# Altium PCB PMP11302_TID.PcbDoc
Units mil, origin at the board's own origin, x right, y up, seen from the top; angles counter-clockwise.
Board outline 1771.65 x 1496.06 mil, 2 copper layers (Top Layer, Bottom Layer), stack 62 mil thick; 48 components, 26 nets, 99 pads, 6 vias.
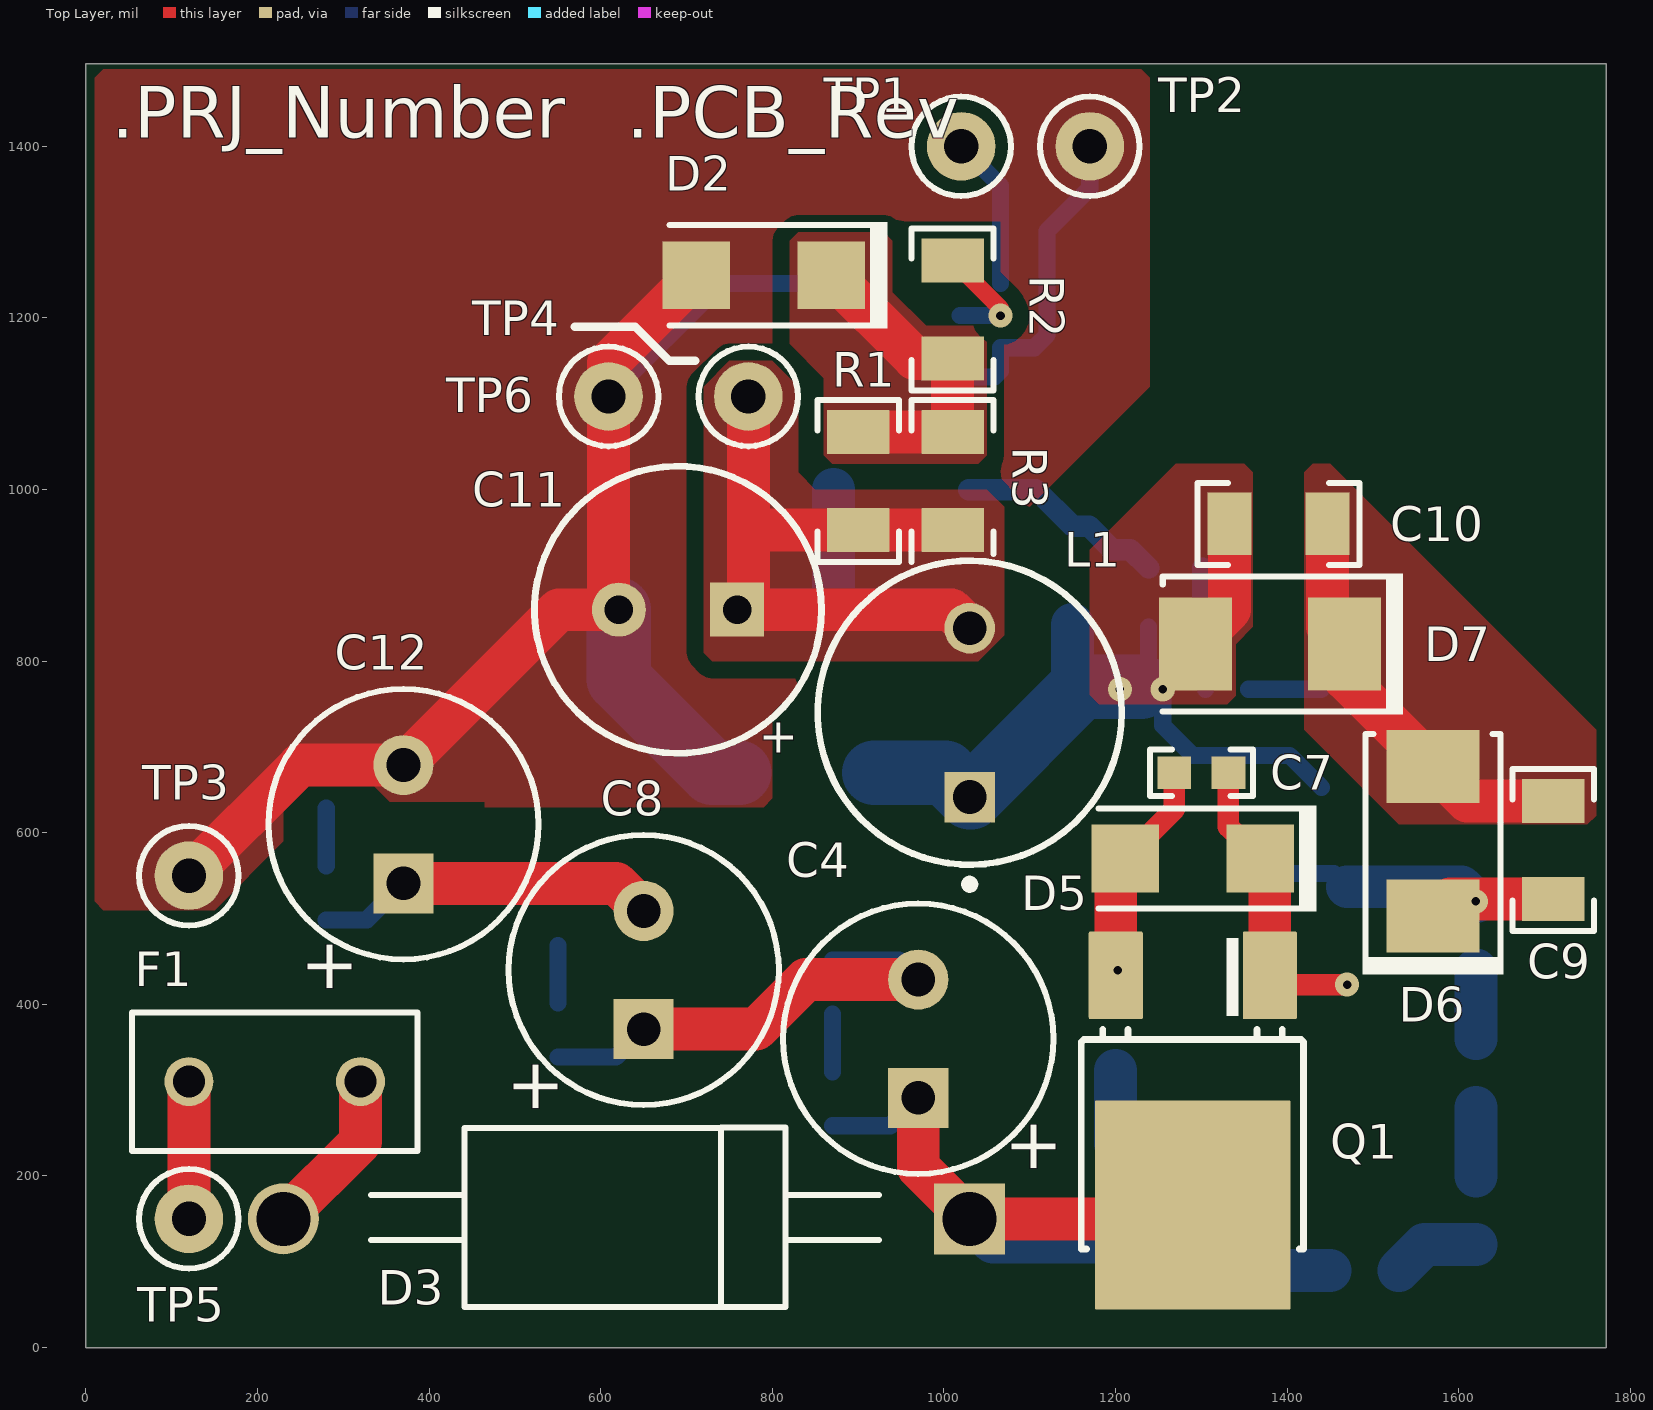
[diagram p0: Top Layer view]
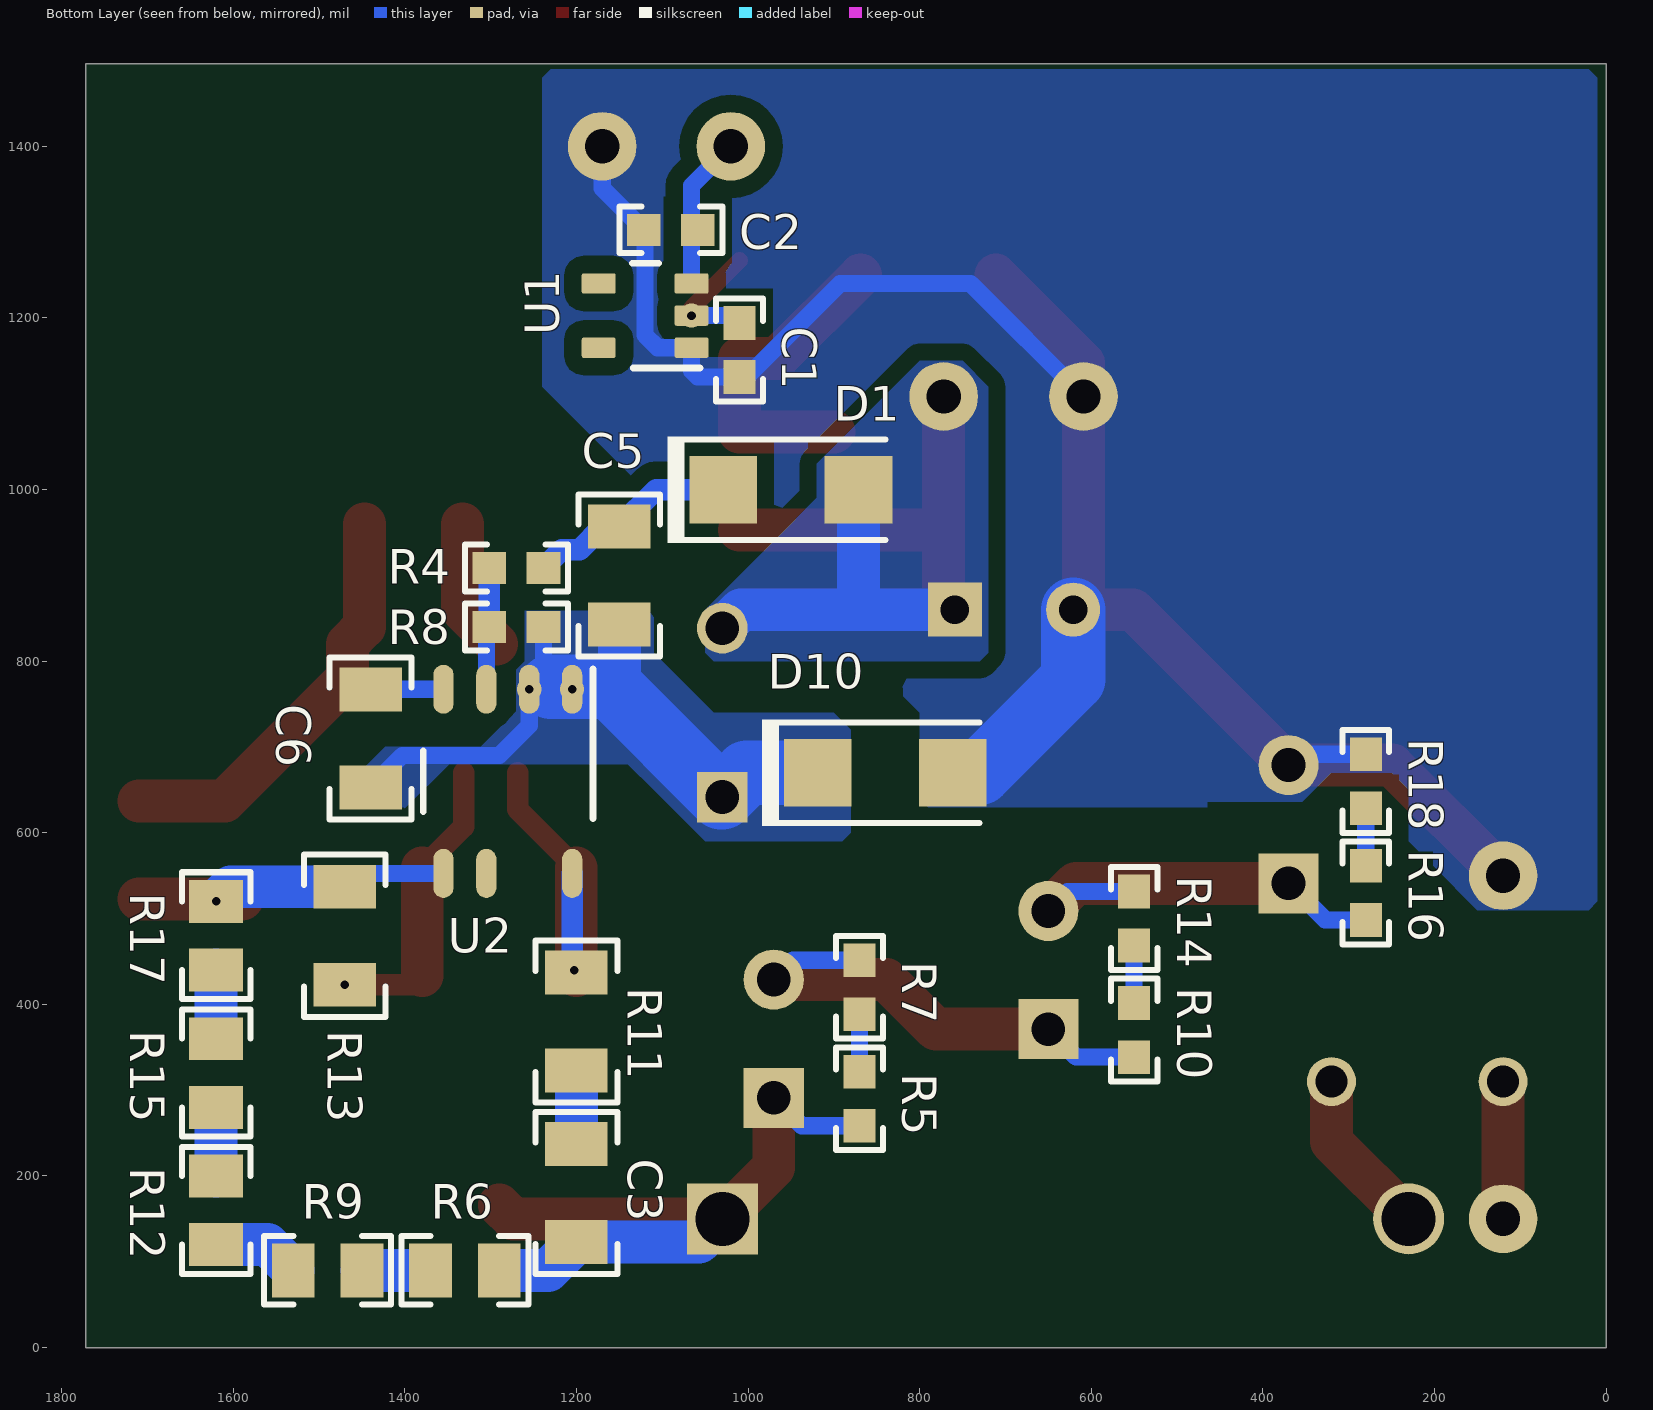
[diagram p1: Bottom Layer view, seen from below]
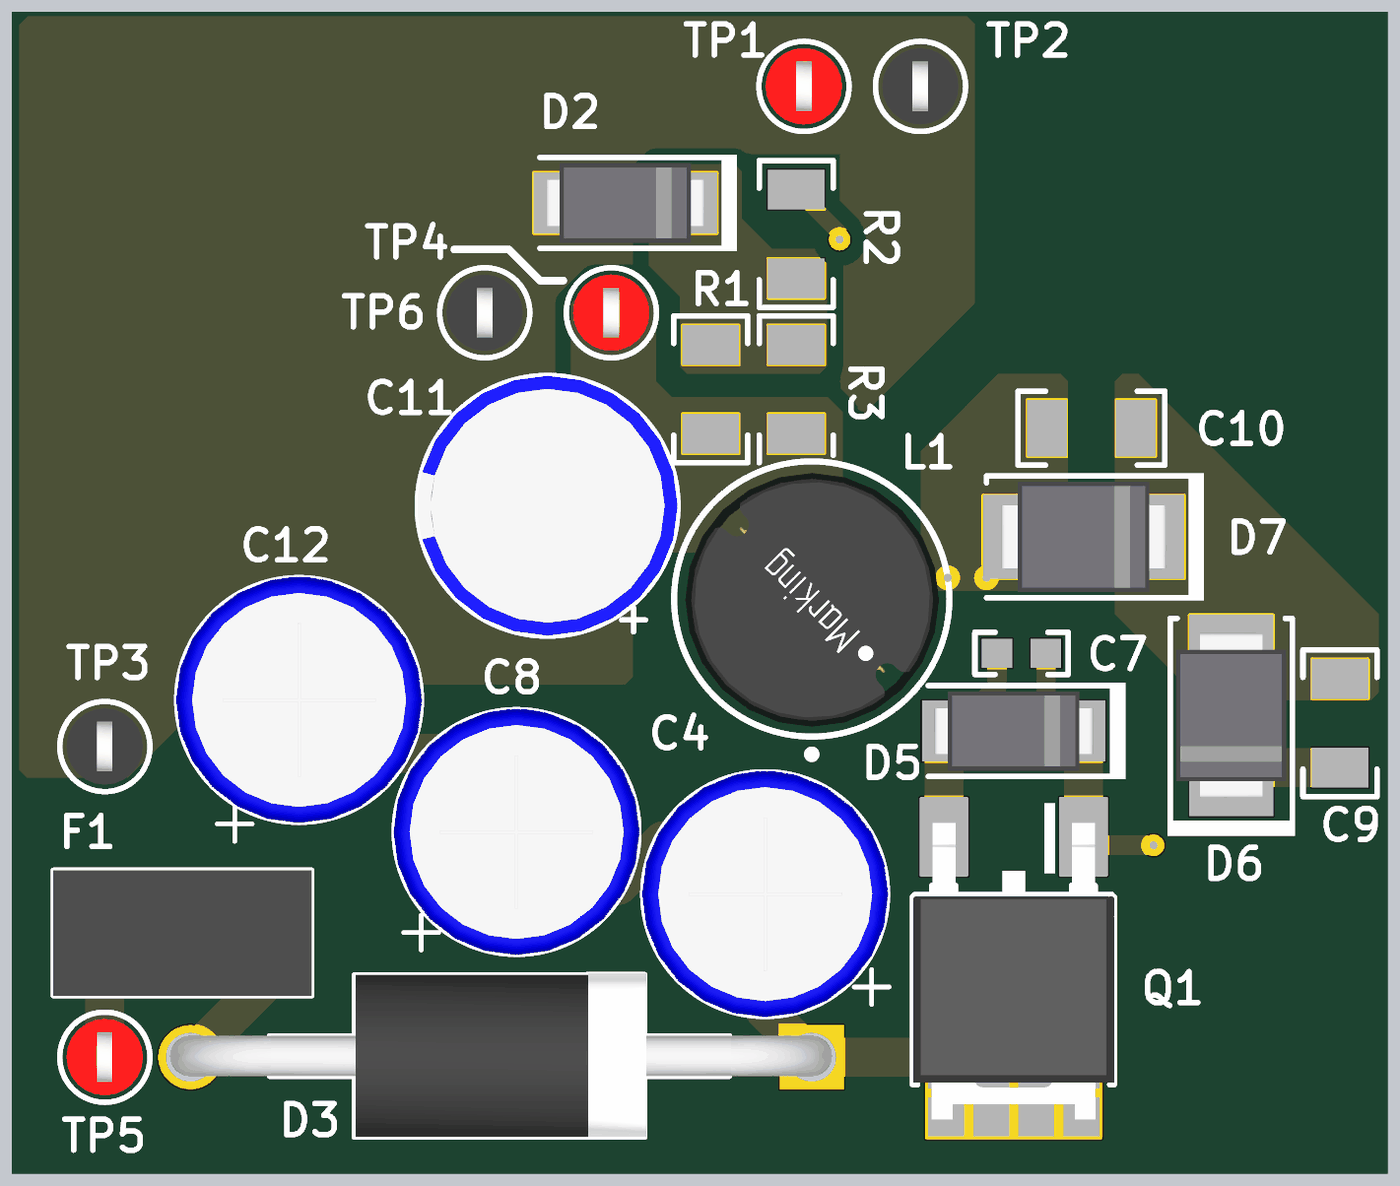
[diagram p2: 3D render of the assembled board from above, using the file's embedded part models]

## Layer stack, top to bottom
Top Solder: solder mask 0.4, Solder Resist, Dk 3.5
Top Layer: signal copper 1.4
Dielectric1: core 59.2, FR-4, Dk 4.8
Bottom Layer: signal copper 1.4
Bottom Solder: solder mask 0.4, Solder Resist, Dk 3.5

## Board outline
0,0 1771.65,0 1771.65,1496.06 0,1496.06

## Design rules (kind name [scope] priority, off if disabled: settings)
AcuteAngle [All] p1: minimum=4.50000000000000E+0001 checktracksonly=FALSE
AssemblyTestPointUsage [All] p1: valid=2
Clearance Clearance_1 [InNetClass('HV') vs InNet('GND')] p1: gap=60
Clearance Clearance_Keepouts [((IsTrack Or IsArc) And Not InPoly) And IsFree and IsKeepOut vs ((IsTrack Or IsArc) And Not InPoly) And IsFree and IsKeepOut] p2: gap=0
Clearance Clearance_BoardEdge_MountingHoles [OnCopper and InComponentClass('Mounting Holes') vs IsKeepOut] p3: gap=40
Clearance Clearance_BoardEdge_Poly [OnCopper and InPoly vs IsKeepOut] p4: gap=25
Clearance Clearance_BoardEdge [OnCopper and Not InComponentClass('Logo') and not InComponentClass('FiducialMark') and not InRegion(1000,500,4000,800) and Not IsKeepout vs IsKeepOut] p5: gap=75
Clearance Clearance_Poly [InPolygon] p6: gap=20
Clearance [All] p7: gap=7.87
ComponentClearance ComponentClearance_MountingHoles_FiducialMarks [InComponentClass('Mounting Holes') vs InComponentClass('FiducialMark')] p1: gap=20 collisioncheckmode=3 verticalgap=10 showdistances=FALSE
ComponentClearance ComponentClearance_Shunt [InComponentClass('Header') vs InComponentClass('Shunt')] p2: gap=0 collisioncheckmode=3 verticalgap=0 showdistances=FALSE
ComponentClearance ComponentClearance_Logo [InComponentClass('Logo')] p3: gap=5 collisioncheckmode=3 verticalgap=10 showdistances=FALSE
ComponentClearance ComponentClearance_ScrewToNut [(HasFootprint('NY PMS 440 0025 PH')) vs (HasFootprint('Keystone_1902C'))] p4: gap=20 collisioncheckmode=3 verticalgap=100000 showdistances=FALSE
ComponentClearance ComponentClearance_MountingHoles [InComponentClass('Mounting Holes')] p5: gap=20 collisioncheckmode=3 verticalgap=10 showdistances=FALSE
ComponentClearance ComponentClearance_SmallPassives [HasFootprint('0201*') or HasFootprint('0402*') or HasFootprint('0508') or HasFootprint('0603*') or HasFootprint('0612') or HasFootprint('0805*') or HasFootprint('0815*') or HasFootprint('0830*') or HasFootprint('1206*') or HasFootprint('1210*') or HasFootprint('1808*') or HasFootprint('1812*') or HasFootprint('1825*') or HasFootprint('2010*') or HasFootprint('2220*') or HasFootprint('2225*') or HasFootprint('2512*') or HasFootprint('2728*') or HasFootprint('3518*') vs HasFootprint('0201*') or HasFootprint('0402*') or HasFootprint('0508') or HasFootprint('0603*') or HasFootprint('0612') or HasFootprint('0805*') or HasFootprint('0815*') or HasFootprint('0830*') or HasFootprint('1206*') or HasFootprint('1210*') or HasFootprint('1808*') or HasFootprint('1812*') or HasFootprint('1825*') or HasFootprint('2010*') or HasFootprint('2220*') or HasFootprint('2225*') or HasFootprint('2512*') or HasFootprint('2728*') or HasFootprint('3518*')] p6: gap=20 collisioncheckmode=3 verticalgap=20 showdistances=FALSE
ComponentClearance ComponentClearance_THtoSMT [IsThruComponent vs IsSMTComponent] p7: gap=10 collisioncheckmode=3 verticalgap=10 showdistances=FALSE
ComponentClearance ComponentClearance_THtoTH [IsThruComponent vs IsThruComponent] p8: gap=10 collisioncheckmode=3 verticalgap=10 showdistances=FALSE
ComponentClearance [All] p9: gap=10 collisioncheckmode=3 verticalgap=10 showdistances=FALSE
DiffPairsRouting [All] p1: maxlimit=100 minlimit=10 mostfreqgap=10 toplayer_minwidth=15 toplayer_maxwidth=15 toplayer_prefwidth=15 bottomlayer_minwidth=15 bottomlayer_maxwidth=15 bottomlayer_prefwidth=15 maxuncoupledlength=1000
FabricationTestPointUsage TestPointUsage [All] p1: valid=2 allowmultiple=FALSE
FabricationTestpoint Testpoint [All] p1: side=3 testpointundercomponent=TRUE minsize=40 maxsize=100 preferedsize=60 minholesize=0 maxholesize=40 preferedholesize=32 testpointgrid=1 allowsidetop=TRUE allowsidebottom=TRUE usegrid=TRUE gridtolerance=0.01
FanoutControl Fanout_LCC [IsLCC] p1: bgadir=Out bgaviamode=Centered fanoutstyle=Auto fanoutdirection=Alternating viagrid=1 // Fanout_LCC (Default Rule)
FanoutControl Fanout_BGA [IsBGA] p2: bgadir=Out bgaviamode=Centered fanoutstyle=Auto fanoutdirection=Alternating viagrid=1 // Fanout_BGA (Default Rule)
FanoutControl Fanout_Default [All] p4: bgadir=Out bgaviamode=Centered fanoutstyle=Auto fanoutdirection=Alternating viagrid=1 // Fanout_Default (Default Rule)
FanoutControl Fanout_Small [(CompPinCount < 5)] p5: bgadir=Out bgaviamode=Centered fanoutstyle=Auto fanoutdirection=OutThenIn viagrid=1 // Fanout_Small (Default Rule)
Height [All] p1: minheight=0 maxheight=3000 prefheight=500
HoleSize [All] p1: absolutevalues=TRUE maxlimit=251 minlimit=7 maxpercent=80.000 minpercent=20.000
MinimumAnnularRing MinimumAnnularRing_ThermalPadVias [IsVia and InAnyComponent] p1: minimumring=5.91
MinimumAnnularRing [All] p2: minimumring=9
MinimumSolderMaskSliver MinimumSolderMaskSliver_Logo [InComponentClass('Logo') vs InComponentClass('Logo')] p1: minsoldermaskwidth=0.7
MinimumSolderMaskSliver [All] p2: minsoldermaskwidth=2
PlaneConnect [All] p1: planeconnectstyle=Relief reliefexpansion=10 reliefentries=4 reliefconductorwidth=10 reliefairgap=10
PolygonConnect PolygonConnect_7 [All vs IsNamedPolygon('C9_2') Or  IsNamedPolygon('C5_2') Or  IsNamedPolygon('C11_1') Or  IsNamedPolygon('D2_1')] p1: connectstyle=Direct reliefconductorwidth=10 reliefentries=4 polygonreliefangle="90 Angle" airgapwidth=10
PolygonConnect PolygonConnect_6 [All vs IsNamedPolygon('GND2') Or  IsNamedPolygon('SGND') Or  IsNamedPolygon('GND1') Or  IsNamedPolygon('C901_1') Or  IsNamedPolygon('SGND') Or  IsNamedPolygon('GND2') Or  IsNamedPolygon('GND1')] p2: connectstyle=Direct reliefconductorwidth=10 reliefentries=4 polygonreliefangle="90 Angle" airgapwidth=10
PolygonConnect PolygonConnect_5 [All vs IsNamedPolygon('GND1') Or  IsNamedPolygon('GND1')] p3: connectstyle=Direct reliefconductorwidth=10 reliefentries=4 polygonreliefangle="90 Angle" airgapwidth=10
PolygonConnect PolygonConnect_4 [All vs IsNamedPolygon('C21_1') Or  IsNamedPolygon('C5_1') Or  IsNamedPolygon('C12_2') Or  IsNamedPolygon('C2_2') Or  IsNamedPolygon('C13_1') Or  IsNamedPolygon('C28_1') Or  IsNamedPolygon('C6_1') Or  IsNamedPolygon('GND') Or  IsNamedPolygon('GND2') Or  IsNamedPolygon('C14_1') Or  IsNamedPolygon('C13_1') Or  IsNamedPolygon('Q1_3') Or  IsNamedPolygon('C14_1') Or  IsNamedPolygon('C5_1') Or  IsNamedPolygon('GND2') Or  IsNamedPolygon('C28_1') Or  IsNamedPolygon('D5_2') Or  IsNamedPolygon('D6_2') Or  IsNamedPolygon('D2_1') Or  IsNamedPolygon('C12_2') Or  IsNamedPolygon('D2_1') Or  IsNamedPolygon('C4_1') Or  IsNamedPolygon('C4_1') Or  IsNamedPolygon('C2_2') Or  IsNamedPolygon('GND') Or  IsNamedPolygon('C33_1') Or  IsNamedPolygon('C9_1')] p4: connectstyle=Direct reliefconductorwidth=10 reliefentries=4 polygonreliefangle="90 Angle" airgapwidth=10
PolygonConnect PolygonConnect_3 [All vs IsNamedPolygon('C28_1') Or  IsNamedPolygon('C12_2') Or  IsNamedPolygon('C28_1') Or  IsNamedPolygon('C9_1') Or  IsNamedPolygon('D5_2') Or  IsNamedPolygon('C12_2') Or  IsNamedPolygon('C2_2') Or  IsNamedPolygon('C14_1') Or  IsNamedPolygon('C4_1') Or  IsNamedPolygon('C14_1') Or  IsNamedPolygon('D6_2') Or  IsNamedPolygon('GND2') Or  IsNamedPolygon('Q1_3') Or  IsNamedPolygon('C5_1') Or  IsNamedPolygon('D2_1') Or  IsNamedPolygon('C4_1') Or  IsNamedPolygon('C13_1') Or  IsNamedPolygon('C5_1') Or  IsNamedPolygon('C13_1') Or  IsNamedPolygon('C33_1') Or  IsNamedPolygon('D2_1') Or  IsNamedPolygon('GND') Or  IsNamedPolygon('GND') Or  IsNamedPolygon('GND2') Or  IsNamedPolygon('C2_2') Or  IsNamedPolygon('C6_1') Or  IsNamedPolygon('C21_1')] p5: connectstyle=Direct reliefconductorwidth=10 reliefentries=4 polygonreliefangle="90 Angle" airgapwidth=10
PolygonConnect PolygonConnect_2 [All vs IsNamedPolygon('C21_1') Or  IsNamedPolygon('C4_1') Or  IsNamedPolygon('D5_2') Or  IsNamedPolygon('C5_1') Or  IsNamedPolygon('C14_1') Or  IsNamedPolygon('C13_1') Or  IsNamedPolygon('C4_1') Or  IsNamedPolygon('C33_1') Or  IsNamedPolygon('C12_2') Or  IsNamedPolygon('D2_1') Or  IsNamedPolygon('C2_2') Or  IsNamedPolygon('C28_1') Or  IsNamedPolygon('C12_2') Or  IsNamedPolygon('D2_1') Or  IsNamedPolygon('C5_1') Or  IsNamedPolygon('Q1_3') Or  IsNamedPolygon('GND') Or  IsNamedPolygon('D6_2') Or  IsNamedPolygon('C6_1') Or  IsNamedPolygon('C2_2') Or  IsNamedPolygon('C14_1') Or  IsNamedPolygon('C28_1') Or  IsNamedPolygon('C13_1') Or  IsNamedPolygon('C9_1') Or  IsNamedPolygon('GND')] p6: connectstyle=Direct reliefconductorwidth=10 reliefentries=4 polygonreliefangle="90 Angle" airgapwidth=10
PolygonConnect PolygonConnect_1 [All vs IsNamedPolygon('C28_1') Or  IsNamedPolygon('D5_2') Or  IsNamedPolygon('C5_1') Or  IsNamedPolygon('C5_1') Or  IsNamedPolygon('D2_1') Or  IsNamedPolygon('C21_1') Or  IsNamedPolygon('C9_1') Or  IsNamedPolygon('C4_1') Or  IsNamedPolygon('C14_1') Or  IsNamedPolygon('C28_1') Or  IsNamedPolygon('C6_1') Or  IsNamedPolygon('C12_2') Or  IsNamedPolygon('C33_1') Or  IsNamedPolygon('C4_1') Or  IsNamedPolygon('C13_1') Or  IsNamedPolygon('C12_2') Or  IsNamedPolygon('D6_2') Or  IsNamedPolygon('C2_2') Or  IsNamedPolygon('C14_1') Or  IsNamedPolygon('D2_1') Or  IsNamedPolygon('C2_2') Or  IsNamedPolygon('C13_1')] p7: connectstyle=Direct reliefconductorwidth=10 reliefentries=4 polygonreliefangle="90 Angle" airgapwidth=10
PolygonConnect [All] p8: connectstyle=Relief reliefconductorwidth=10 reliefentries=4 polygonreliefangle="90 Angle" airgapwidth=10
RoutingVias ThermalPadVias [IsVia and InAnyComponent] p1: holewidth=7.87 width=19.68 viastyle="Through Hole" minholewidth=7.87 minwidth=19.68 maxholewidth=12.99 maxwidth=23.62
RoutingVias [All] p2: holewidth=16 width=34 viastyle="Through Hole" minholewidth=7.87 minwidth=26 maxholewidth=40 maxwidth=65
SilkToBoardRegionClearance [Not ((IsComment or IsDesignator) And (Hide <> 'False')) and not InRegion(1000,500,4000,800)] p1:
SilkToSilkClearance SilkToSilkClearance_Pb-FreeLogo [(HasFootprint('Pb-Free_Overlay_Medium') OR HasFootprint('Pb-Free_Overlay_Small')) vs (HasFootprint('Pb-Free_Overlay_Medium') OR HasFootprint('Pb-Free_Overlay_Small'))] p1: silktosilkclearance=0
SilkToSilkClearance [All] p2: silktosilkclearance=1
SilkToSolderMaskClearance "Silk to Solder Mask Opening" [All] p1: minsilkscreentomaskgap=1 clearancetoexposedcopper=FALSE
SolderMaskExpansion [All] p1: expansion=1.97
UnpouredPolygon [All] p1: allowunpoured=FALSE
Width [All] p1: maxlimit=100 minlimit=6 preferedwidth=10 checkconnectedcopper=TRUE
13 further rules are at their usual default settings.

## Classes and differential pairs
net class HV: NetC3_1 NetC3_2 NetC4_2 NetC5_2 NetC7_1 NetC7_2 NetC8_2 NetC9_2 NetD3_2 NetF1_2 NetR4_1 NetR6_1 NetR9_1 NetR12_1 NetR15_1 VIN

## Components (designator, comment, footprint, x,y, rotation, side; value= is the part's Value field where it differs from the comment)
C1 "06033C104JAT2A" 0603 1010,1162.76 r270 bottom
C2 "C0603C105K4PACTU" 0603 1090,1302.76 r0 bottom
C3 "VJ1206A470JXGAT5Z" 1206 1200,180 r90 bottom
C4 "400AX6R8M8x11" CAPPRD350W60D800H1100 970,360 r90 top
C5 "12065C104JAT2A" 1206 1150,900 r270 bottom
C6 "12065C223KAT2A" 1206 1440,710 r270 bottom
C7 "06035A102KAT2A" 0603 1300,670 r180 top
C8 "400AX6R8M8x11" CAPPRD350W60D800H1100 650,440 r90 top
C9 "GRM31A7U3A470JW31D" 1206 1710,580 r90 top
C10 "GRM31A7U3A470JW31D" 1206 1390,960 r180 top
C11 "UPW1V151MPD" HE_800x1150 690,860 r180 top
C12 "400AX6R8M8x11" CAPPRD350W60D800H1100 370,610 r90 top
D1 "ES1M-TP" SMA 950,1000 r180 bottom
D2 "1SMA5927BT3G" SMA 790,1250 r180 top
D3 "BY255GP-E3/54" DO-201AD 630,150 r180 top
D5 "1SMA5927BT3G" SMA 1290,570 r180 top
D6 "SMBJ300A" SMB 1570,590 r90 top
D7 "SMBJ300A" SMB 1380,820 r180 top
D10 "US1M-E3/5AT" SMA 840,670 r180 bottom
F1 "RST 500" Fuse_RST 220,310 r180 top
L1 "744741222" WE-TI_8055 1030,740 r90 top
Q1 "STD8N65M5" DPAK 1290,300 r270 top
R1 "CRCW12061K50FKEA" 1206 900,1010 r90 top
R2 "CRCW1206100RFKEA" 1206 1010,1210 r90 top
R3 "CRCW12061K50FKEA" 1206 1010,1010 r90 top
R4 "RC0603FR-07237KL" 0603 1270,908.58 r180 bottom
R5 "CRCW06031M00JNEA" 0603 870,290 r270 bottom
R6 "CRCW0805470KJNEA" 0805_HV 1330,90 r180 bottom
R7 "CRCW06031M00JNEA" 0603 870,420 r270 bottom
R8 "CRCW060310K0FKEA" 0603 1270,840 r0 bottom
R9 "CRCW0805470KJNEA" 0805_HV 1490,90 r180 bottom
R10 "CRCW06031M00JNEA" 0603 550,370 r270 bottom
R11 "CRCW120610R0FKEA" 1206 1200,380 r270 bottom
R12 "CRCW0805470KJNEA" 0805_HV 1620,160 r270 bottom
R13 "CRCW120610R0FKEA" 1206 1470,480 r270 bottom
R14 "CRCW06031M00JNEA" 0603 550,500 r270 bottom
R15 "CRCW0805470KJNEA" 0805_HV 1620,320 r270 bottom
R16 "CRCW06031M00JNEA" 0603 280,530 r270 bottom
R17 "CRCW0805470KJNEA" 0805_HV 1620,480 r270 bottom
R18 "CRCW06031M00JNEA" 0603 280,660 r270 bottom
TP1 "5000" Keystone5000 1020,1400 r0 top
TP2 "5001" Keystone5001 1170,1400 r0 top
TP3 "5001" Keystone5001 120,550 r0 top
TP4 "5000" Keystone5000 772.05,1108.5 r0 top
TP5 "5000" Keystone5000 120,150 r0 top
TP6 "5001" Keystone5001 609.05,1108.5 r0 top
U1 "TLV70450DBVT" DBV0005A_N 1120,1202.76 r0 bottom
U2 "UCC28881DR" D0007A_N 1280,660 r270 bottom

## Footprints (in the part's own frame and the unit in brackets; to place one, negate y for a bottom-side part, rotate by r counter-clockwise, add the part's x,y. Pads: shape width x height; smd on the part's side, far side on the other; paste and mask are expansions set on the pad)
0603 [mm] "0603 from SM-752 data"
  rect 1x0.95 smd: 1(-0.8,0) 2(0.8,0)
  silkscreen extent -1.52,-0.69 1.52,0.69, body extent -0.87,-0.47 0.87,0.47, height 1
0805_HV [mil] "0805 with 30mil clearance between pads"
  rect 50x63 smd: 1(-40,0) 2(40,0)
  silkscreen extent -74,-40 74,40, body extent -43,-29 43,29, height 57
1206 [mm] "1206 from SM-752 data"
  rect 1.3x1.85 smd: 1(-1.45,0) 2(1.45,0)
  silkscreen extent -2.4,-1.21 2.4,1.21, body extent -1.7,-0.9 1.7,0.9, height 1.35
CAPPRD350W60D800H1100 [mm] "Capacitor, Alum, 8x11mm"
  rect 1.78x1.78 hole 1: 1(-1.75,0)
  round 1.78 hole 1: 2(1.75,0)
  silkscreen extent -4,-4 4,4, body extent -4.03,-4.03 4.03,4.02, height 11.79
D0007A_N [mm] "SOIC, 7-Leads, Body 4.9x3.9mm, Pitch 1.27mm, IPC Medium Density"
  oval 1.45x0.6 smd: 1(-2.725,1.905) 2(-2.725,0.635) 3(-2.725,-0.635) 4(-2.725,-1.905) 5(2.725,-1.905) 6(2.725,-0.635) 8(2.725,1.905)
  silkscreen extent -3.32,-2.5 1.1,2.52, body extent -3.01,-2.45 3.01,2.45, height 1.75
DBV0005A_N [mm] "SOT23, 5-Leads, Body 2.9x1.6mm, Pitch 0.95mm, Lead Span 2.8mm, IPC Medium Density"
  rrect17% 1x0.6 smd: 1(-1.375,0.95) 2(-1.375,0) 3(-1.375,-0.95) 4(1.375,-0.95) 5(1.375,0.95)
  silkscreen extent -1.63,-1.55 0.38,1.55, body extent -1.42,-1.46 1.42,1.46, height 1.09
DO-201AD [mm] "Vishay dimensions"
  rect 2.1x2.1 hole 1.6: 1(-10.16,0)
  round 2.1 hole 1.6: 2(10.16,0)
  silkscreen extent -7.47,-2.7 7.57,2.61, body extent -10.82,-2.74 10.82,2.61, height 5.33
DPAK [mm] "D-PAK, 3-Pads, Body 6.22x6.73mm (max), TO-252AA using nominal STEP model"
  rrect6% 2.6x1.6 smd: 1(-3.4,2.28) 3(-3.4,-2.28)
  rrect2% 6.2x5.8 smd paste-2.9: 4(3.4,0)
  silkscreen extent -4.5,-3.3 4.7,3.28, body extent -3.86,-3.29 5.84,3.29, height 2.48
Fuse_RST [mm] "Bel Fuse RST series May2012D"
  round 1.45 hole 0.95: 1(-2.54,0) 2(2.54,0)
  silkscreen extent -4.23,-2.05 4.23,2.05, body extent -4.22,-2.05 4.23,2.05, height 7.9
HE_800x1150 [mm] "NICHICON"
  rect 1.6x1.6 hole 0.838: 1(-1.75,0)
  round 1.6 hole 0.838: 2(1.75,0)
  silkscreen extent -4.25,-4.25 4.25,4.25, body extent -4.22,-4.24 4.24,4.24, height 11.51
Keystone5000 [mil] "For Keystone 500x miniature loop terminals"
  round 80 hole 40: 1(0,0)
  silkscreen extent -58,-58 58,58, body extent -49,-49 49,49, height 182
Keystone5001 [mil] "For Keystone 500x miniature loop terminals"
  round 80 hole 40: 1(0,0)
  silkscreen extent -58,-58 58,58, body extent -49,-49 49,49, height 182
SMA [mm] "Molded Diode, 2-Leads, Body 4.3x2.6mm, IPC Medium Density, based on OnSemi component dimensions and land pattern"
  rect 2x2 smd: 1(-2,0) 2(2,0)
  silkscreen extent -3.66,-1.57 2.79,1.57, body extent -2.6,-1.3 2.6,1.3, height 2.42
SMB [mil] "Molded Diode, 2-Leads, Body 5.4x3.6mm, IPC Medium Density, based on OnSemi component dimensions"
  rect 85x107.99 smd: 1(-87.01,0) 2(87.01,0)
  silkscreen extent -155,-82 125,82, body extent -106,-71 106,71, height 91
WE-TI_8055 [mm] "Wurth"
  rect 1.5x1.5 hole 1: 1(-2.5,0)
  round 1.5 hole 1: 2(2.5,0)
  silkscreen extent -5.21,-4.5 4.5,4.5, body extent -5.89,-5.88 5.81,5.83, height 5.51

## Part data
C1: "CAP, CERM, 0.1 µF, 25 V, +/- 5%, X7R, 0603"
C2: "CAP, CERM, 1 µF, 16 V, +/- 10%, X5R, 0603"
C3: "CAP, CERM, 47 pF, 1000 V, +/- 5%, C0G/NP0, 1206"
C4 C8 C12: "CAP, AL, 6.8 µF, 400 V, +/- 20%, TH"
C5: "CAP, CERM, 0.1uF, 50V, +/-5%, X7R, 1206"
C6: "CAP, CERM, 0.022uF, 50V, +/-10%, X7R, 1206"
C7: "CAP, CERM, 1000 pF, 50 V, +/- 10%, C0G/NP0, 0603"
C9 C10: "CAP, CERM, 47 pF, 1000 V, +/- 5%, U2J, 1206"
C11: library part UHE1H101MPD, "CAP ALUM 150UF 35V 20% RADIAL"
D1: library part ES1D-13-F, "DIODE GEN PURP 1KV 1A DO214AC"
D2 D5: "Diode, Zener, 12 V, 1.5 W, SMA"
D3: "Diode, P-N, 1300 V, 3 A, TH"
D6 D7: library part SMBJ30A-13-F, "TVS DIODE 300VWM 486VC SMB"
D10: library part US1K-13-F, "DIODE GEN PURP 1KV 1A DO214AC"
F1: "Fuse, 0.5 A, 250 V, TH"
L1: library part 744741101, "FIXED IND 2.2MH 210MA 11 OHM TH"
Q1: library part STD13NM60N, "MOSFET N-CH 650V 7A DPAK"
R1 R3: "RES, 1.50 k, 1%, 0.25 W, 1206"
R2: "RES, 100, 1%, 0.25 W, 1206"
R4: "RES, 237 k, 1%, 0.1 W, 0603"
R5 R7 R10 R14 R16 R18: "RES, 1.0 M, 5%, 0.1 W, 0603"
R6 R9 R12 R15 R17: "RES, 470 k, 5%, 0.125 W, 0805"
R8: "RES, 10.0k ohm, 1%, 0.1W, 0603"
R11 R13: "RES, 10.0, 1%, 0.25 W, 1206"
TP1 TP4 TP5: "Test Point, Miniature, Red, TH"
TP2 TP3 TP6: "Test Point, Miniature, Black, TH"
U1: "Single Output LDO, 150 mA, Fixed 5 V Output, 2.5 to 24 V Input, with Ultra-Low IQ, 5-pin SOT-23 (DBV), -40 to 125 degC, Green (RoHS & no Sb/Br)"
U2: "700-V Lowest Quiescent Current Off-Line Switcher, D0007A"

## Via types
v1: diameter 28, hole 10, Top Layer to Bottom Layer, 6 vias

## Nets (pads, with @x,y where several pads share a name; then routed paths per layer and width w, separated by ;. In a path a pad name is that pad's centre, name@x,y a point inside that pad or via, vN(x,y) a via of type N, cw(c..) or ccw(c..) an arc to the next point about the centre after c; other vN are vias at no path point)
GND: C1.2 C2.2 C11.2 C12.2 D2.2 D10.2 R18.1 TP2.1 TP3.1 TP6.1 U1.1 | length 2298.6
  Top Layer w50: TP3.1 248.9,678.9 C12.2 551.1,860 C11.2 ; C11.2@609.05,872.05 TP6.1 609.05,1147.79 D2.2
  Bottom Layer w20: R18.1 357.4,691.5 C12.2 ; TP6.1 740.55,1240 892.91,1240 1001.65,1131.26 C1.2 1058.9,1131.26 1065.87,1138.23 U1.1 1105.35,1165.35 1120,1180 1120,1301.26 C2.2 1170,1351.26 TP2.1
  Bottom Layer w75: C11.2 621.1,778.9 730,670 D10.2
NetC1_1: C1.1 R2.2 U1.2 | length 134.8
  Top Layer w20: R2.2 1065.87,1211.22 v1(1065.87,1202.76)
  Bottom Layer w20: C1.1@1018.5,1202.76 v1(1065.87,1202.76)
NetC2_1: C2.1 TP1.1 U1.3 | length 178.8
  Bottom Layer w20: TP1.1 1065.87,1354.13 U1.3
NetC3_1: C3.1 C4.1 D3.1 Q1.4 R5.2 R6.2 | length 831
  Top Layer w50: C4.1 970,210 D3.1 1273.86,150 Q1.4
  Bottom Layer w20: R5.2 937.4,258.5 C4.1
  Bottom Layer w50: D3.1 1057.09,122.91 C3.1 1232.91,90 R6.2
NetC3_2: C3.2 R11.2 | length 85.8
  Bottom Layer w50: C3.2 R11.2
NetC4_2: C4.2 C8.1 R7.1 R10.2 | length 566.8
  Top Layer w50: C8.1 781.1,371.1 838.9,428.9 C4.2
  Bottom Layer w20: R10.2 617.4,338.5 C8.1 ; R7.1 947.4,451.5 C4.2
NetC5_1: C5.1 D1.1 R4.2 | length 247.6
  Bottom Layer w25: D1.1 1107.09,1000 C5.1 1169.17,957.09 1196.26,930 1217.09,930 R4.2
NetC5_2: C5.2 C6.2 C10.2 D7.2 D10.1 L1.1 R8.1 U2.1 U2.2 | length 928.5
  Top Layer w50: D7.2 1332.91,859.92 C10.2
  Bottom Layer w20: 1238.5,778.5 R8.1 ; v1(1255,767.28) 1255,725 1290,690 1402.91,690 C6.2
  Bottom Layer w50: C5.2 1150,780 1160,770
  Bottom Layer w75: D10.1 1001.57,670 L1.1 1031.57,641.57 1160,770 1230,770
  other v1: 1205,767.28
NetC6_1: C6.1 U2.4 | length 84.8
  Bottom Layer w20: U2.4 C6.1@1439.8,767.28
NetC7_1: C7.1 D5.1 Q1.1 R13.2 | length 319.8
  Top Layer w25: C7.1 1331.5,607.24 D5.1 ; Q1.1@1390.71,422.91 v1(1470,422.91)
  Top Layer w50: Q1.1 D5.1@1379.76,558.98
NetC7_2: C7.2 D5.2 Q1.3 R11.1 U2.8 | length 366.5
  Top Layer w25: D5.2 1268.5,627.24 C7.2
  Top Layer w50: Q1.3 D5.2@1200.24,558.98
  Bottom Layer w25: R11.1 1205,442.09 U2.8
  other v1: 1202.5,439.59
NetC8_2: C8.2 C12.1 R14.1 R16.2 | length 510.3
  Top Layer w50: C12.1 617.8,541.1 C8.2
  Bottom Layer w20: R16.2 327.4,498.5 C12.1 ; R14.1 627.4,531.5 C8.2
NetC9_2: C9.2 C10.1 D6.2 D7.1 | length 490.4
  Top Layer w50: C10.1 1447.09,839.92 D7.1 1467.01,780 D6.2 1609.92,637.09 C9.2
NetC11_1: C11.1 D1.2 L1.2 R1.1 R3.1 TP4.1 | length 1155
  Top Layer w50: C11.1 1008.43,860 L1.2 ; C11.1@772.05,873.15 TP4.1 ; 779.14,952.91 R1.1 R3.1
  Bottom Layer w50: C11.1 1008.43,860 L1.2 ; 871.26,871.26 D1.2
NetD2_1: D2.1 R1.2 R2.1 R3.2 | length 377.3
  Top Layer w50: D2.1 965.83,1152.91 R2.1 R3.2 R1.2
NetD3_2: D3.2 F1.1 | length 197.3
  Top Layer w50: D3.2 320,240 F1.1
NetF1_2: F1.2 TP5.1 | length 160
  Top Layer w50: TP5.1 F1.2
NetR4_1: R4.1 R8.2 U2.3 | length 137.8
  Bottom Layer w20: U2.3 R8.2@1305,836.5
  Bottom Layer w25: R8.2 R4.1
NetR5_1: R5.1 R7.2 | length 67
  Bottom Layer w20: R5.1 R7.2
NetR6_1: R6.1 R9.2 | length 80
  Bottom Layer w50: R6.1 R9.2
NetR9_1: R9.1 R12.2 | length 102.4
  Bottom Layer w50: R9.1 1560,120 R12.2
NetR10_1: R10.1 R14.2 | length 67
  Bottom Layer w20: R10.1 R14.2
NetR12_1: R12.1 R15.2 | length 80
  Bottom Layer w50: R12.1 R15.2
NetR15_1: R15.1 R17.2 | length 80
  Bottom Layer w50: R15.1 R17.2
NetR16_1: R16.1 R18.2 | length 67
  Bottom Layer w20: R16.1 R18.2
VIN: C9.1 D6.1 R13.1 R17.1 U2.5 | length 398.6
  Top Layer w50: D6.1@1589.92,522.91 C9.1
  Bottom Layer w20: U2.5 1454.37,552.72 R13.1
  Bottom Layer w50: R13.1 1602.91,537.09 v1(1620,520)
pads on no net: U1.4 U1.5 U2.6

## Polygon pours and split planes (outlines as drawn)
GND on Top Layer "GND" (solid, remove dead copper, pour order 14): 20,510 10,520 10,550 10,870 10,1350 10,1480 20,1490 40,1490 1230,1490 1240,1480 1240,1470 1240,1390 1240,1120 1140,1020 920,800 880,800 860,800 800,740 800,728.5 800,670 800,640 790,630 750,630 360,630 320,670 298.7,670 250,670 230,650 230,620 230,590 150,510
NetD2_1 on Top Layer "D2_1" (solid, remove dead copper, pour order 8): 830,1300 820,1290 820,1280 820,1181.1 820,1170 860,1130 860,1120 860,1040 870,1030 880,1030 1040,1030 1050,1040 1050,1068.9 1050,1178.54 1038.54,1190 1037.74,1190.81 991.32,1190.81 979.19,1190.81 940,1230 940,1290 930,1300
NetC11_1 on Top Layer "C11_1" (solid, remove dead copper, pour order 6): 730,800 720,810 720,840 720,1040 720,1120 750,1150 770,1150 800,1150 820,1130 830,1120 830,1068.98 829.92,1068.9 829.92,1030 829.92,1020.08 830,1020 850,1000 853.74,1000 1050,1000 1070,980 1070,970 1070,830 1040,800 1020,800 730,800
NetC9_2 on Top Layer "C9_2" (solid, remove dead copper, pour order 4): 1430,1030 1420,1020 1420,980 1420,860 1420,720 1510,630 1530.31,609.69 1570,609.69 1749.69,609.69 1760,620 1760,680 1760,720 1450,1030
NetC5_2 on Top Layer "C5_2" (solid, remove dead copper, pour order 2): 1360,1020 1350,1030 1330,1030 1270,1030 1170,930 1170,890 1170,760.59 1180.59,750 1220,750 1330,750 1340,760 1340,780 1340,820 1360,840
GND on Bottom Layer "GND" (solid, remove dead copper, pour order 14): 20,510 10,520 10,550 10,870 10,1350 10,1480 20,1490 40,1490 1230,1490 1240,1480 1240,1470 1240,1390 1240,1120 1140,1020 920,800 880,800 860,800 800,740 800,728.5 800,670 800,640 790,630 750,630 360,630 320,670 298.7,670 250,670 230,650 230,620 230,590 150,510
NetC5_2 on Bottom Layer "C5_2" (solid, remove dead copper, pour order 12): 1110,860 1110,810 1100,800 1080,780 1040,740 900,740 880,720 880,700 880,600 890,590 910,590 1050,590 1110,650 1140,680 1300,680 1348.5,680 1400,628.5 1401.5,630 1460,630 1460,662.76 1422.76,700 1420,700 1311.5,700 1270,741.5 1270,790 1260,800 1260,811.46 1260,858.7 1235.55,858.7 1115.87,858.7 1114.57,860
NetC11_1 on Bottom Layer "C11_1" (solid, remove dead copper, pour order 10): 730,800 720,810 720,970 720,1120 750,1150 800,1150 830,1120 919.69,1030.31 919.69,1010 919.69,990.31 1040,870 1050,860 1050,850 1050,810 1040,800

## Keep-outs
Keep-Out Layer:
  text ".Layer_Name" at 577,-858.49 h60

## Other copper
Top Layer:
  text ".Layer_Name" at 577,-858.49 h60
Bottom Layer:
  text ".Layer_Name" at 577,-858.49 h60

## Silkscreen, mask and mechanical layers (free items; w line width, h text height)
Top Overlay:
  lines w10: 570,1190 640,1190 680,1150 710,1150
  text ".PRJ_Number" at 30,1410 h60
  text ".PCB_Rev" at 630,1410 h60
  text ".Layer_Name" at 577,-858.49 h60
Bottom Overlay:
  text ".Layer_Name" at 577,-858.49 h60
Top Paste:
  text ".Layer_Name" at 577,-858.49 h60
Bottom Paste:
  text ".Layer_Name" at 577,-858.49 h60
Top Solder:
  text ".Layer_Name" at 577,-858.49 h60
  text ".Layer_Name" at 577,-858.49 h60
Bottom Solder:
  text ".Layer_Name" at 577,-858.49 h60
Drill Guide:
  text ".Layer_Name" at 577,-858.49 h60
M1 Board Outline:
  the board outline again, w7.01
  text ".Layer_Name" at 577,-858.49 h60
M2 Board Dimensions:
  rectangle: 125,-400 500,-275
  rectangle: 0,-275 125,-150
  lines w7: 0,-275 1000,-275 ; 125,-400 125,-150 ; 250,-400 250,-150 ; 500,-400 500,-150 ; 750,-400 750,-150 ; 0,-400 0,-150 1000,-150 1000,-400 0,-400
  text ".Layer_Name" at 577,-858.49 h60
M3 3D STEP Top:
  text ".Layer_Name" at 577,-858.49 h60
M4 3D STEP Bottom:
  text ".Layer_Name" at 577,-858.49 h60
M5 Assembly Top:
  lines w10: -292,-930.17 6308,-930.17 ; -292,-726.83 6310,-726.83 ; -292,-523.5 -292,-1133.5 3713,-1133.5 6310,-1133.5 6310,-523.5 -291.5,-523.5 -291.5,-1133.5 1284,-1133.5 ; 2173,-1133.5 2173,-523.5 ; 3440,-726.83 3440,-523.5 ; 4280,-726.83 4280,-523.5 ; 4902,-1140 4902,-937.17
  text "COMPONENTS MARKED 'DNP' SHOULD NOT BE POPULATED." at 1153.5,-318.5 h60
  text "ASSEMBLY VARIANT:" at 1153,-434 h60
  text ".VariantName" at 2189,-434 h60
  text "PCB VIEWED FROM TOP SIDE" at -228.5,-655.67 h60
  text "BOARD #:" at 2248,-655.67 h60
  text ".PRJ_Number" at 2793.5,-655.67 h60
  text "REV:" at 3638,-655.67 h60
  text ".PCB_Rev" at 3929.5,-655.67 h60
  text "SVN REV:" at 4476,-655.67 h60
  text ".VersionControl_RevNumber" at 4982,-655.67 h60
  text "TID #:" at 2248,-859 h60
  text ".TID" at 2793.5,-859 h60
  text "PLOT NAME =" at -228.5,-1064.34 h60
  text ".plot_File_Name" at 577,-1064.34 h60
  text "GENERATED    :" at 2250,-1064.34 h60
  text ".Print_Date" at 3119.5,-1064.34 h60
  text ".Print_Time" at 3848.5,-1064.34 h60
  text "TEXAS INSTRUMENTS" at 5113,-1064.34 h60
M6 Assembly Bottom:
  lines w10: -292.5,-727.33 6309.5,-727.33 ; -290.5,-930.67 6309.5,-930.67 ; 1115.5,-1140.5 1115.5,-937.67 ; 1737.5,-727.33 1737.5,-524 ; 2577.5,-727.33 2577.5,-524 ; 3844.5,-1134 3844.5,-524 ; 4733.5,-1134 6309,-1134 6309,-524 -292.5,-524 -292.5,-1134 2304.5,-1134 6309.5,-1134 6309.5,-524
  text "COMPONENTS MARKED 'DNP' SHOULD NOT BE POPULATED." at 6102,-318 h60
  text ".VariantName" at 5058,-434 h60
  text "ASSEMBLY VARIANT:" at 6097,-434 h60
  text ".VersionControl_RevNumber" at 1035.5,-656.17 h60
  text "SVN REV:" at 1541.5,-656.17 h60
  text ".PCB_Rev" at 2088,-656.17 h60
  text "REV:" at 2379.5,-656.17 h60
  text ".PRJ_Number" at 3224,-656.17 h60
  text "BOARD #:" at 3769.5,-656.17 h60
  text "PCB VIEWED FROM BOTTOM SIDE" at 6246,-656.17 h60
  text ".TID" at 3224,-859.5 h60
  text "TID #:" at 3769.5,-859.5 h60
  text "TEXAS INSTRUMENTS" at 904.5,-1064.84 h60
  text ".Print_Time" at 2169,-1064.84 h60
  text ".Print_Date" at 2898,-1064.84 h60
  text "GENERATED    :" at 3767.5,-1064.84 h60
  text ".plot_File_Name" at 5440.5,-1064.84 h60
  text "PLOT NAME =" at 6246,-1064.84 h60
M9 Title Sheet:
  drawing of 57 lines, arcs and shapes, not listed
  text "1" at 739.84,8036.5 h70
  text "2" at 3235.5,8036.5 h70
  text "3" at 5724.84,8036.5 h70
  text "4" at 8231.51,8036.5 h70
  text "5" at 10730.5,8036.5 h70
  text "6" at 13235.5,8036.5 h70
  text "A" at -416.5,6893.5 h70
  text "A" at 14383.5,6893.5 h70
  text "B" at -416.5,4513.5 h70
  text "B" at 14383.5,4513.5 h70
  text "C" at -416.5,2138.5 h70
  text "C" at 14383.5,2138.5 h70
  text "PROJECT TITLE:" at 11343.5,277.5 h45
  text ".PRJ_Title" at 11393.5,144.17 h70
  text "DESIGNED FOR:" at 11343.5,-23.5 h45
  text ".PRJ_Customer" at 11393.5,-163.5 h70
  text "D" at -416.5,-231.5 h70
  text "D" at 14383.5,-231.5 h70
  text "FILE NAME:" at 11343.5,-323.5 h45
  text ".PCB_File_Name_No_Path" at 11393.5,-443.5 h70
  text "Texas Instruments (TI) and/or its licensors do not warrant the accuracy or completeness of this specification" at 6374,-605.34 h45
  text "ENGINEER:" at 11343.5,-613.5 h45
  text "LAYOUT BY:" at 12848.5,-613.5 h45
  text "or any information contained therein. TI and/or its licensors do not warrant that this design will meet" at 6329.01,-718 h45
  text ".PRJ_Engineer" at 11393.5,-768.49 h70
  text ".PCB_Layout" at 12899,-768.49 h70
  text "the specifications, will be suitable for your application or fit for any particular purpose, or will operate in" at 6329.01,-830.67 h45
  text ".Layer_Name" at 577,-858.49 h60
  text "ALTIUM DESIGNER VERSION:" at 12848.5,-923.5 h45
  text "an implementation. TI and/or its licensors do not warrant that the design is production worthy. You should" at 6329.01,-943.33 h45
  text "completely validate and test your design implementation to confirm the system functionality for your application." at 6374,-1056 h45
  text ".print_Scale" at 11393.5,-1056.83 h70
  text ".Application_BuildNumber" at 12899,-1056.83 h70
  text "1" at 739.84,-1263.5 h70
  text "2" at 3235.5,-1263.5 h70
  text "3" at 5724.84,-1263.5 h70
  text "4" at 8231.51,-1263.5 h70
  text "5" at 10730.5,-1263.5 h70
  text "6" at 13235.5,-1263.5 h70
M10 Fab Notes:
  drawing of 185 lines, arcs and shapes, not listed
  text "DESIGN INFORMATION" at 12381.02,5910 h60
  text "MIN. TRACK WIDTH:" at 11736.46,5730 h60
  text "10" at 12832.7,5730 h60
  text "MIL" at 12987.46,5730 h60
  text "MIN. CLEARANCE:" at 11736.46,5598 h60
  text "0.2" at 12772.7,5598 h60
  text "mm" at 12987.46,5598 h60
  text "MIN. VIA PAD SIZE:" at 11736.46,5466 h60
  text "10" at 12802.71,5466 h60
  text "MIL" at 12987.46,5466 h60
  text "0.05mm (2MIL)" at 12431.46,5324.29 h60
  text "MINIMUM ANNULAR RING" at 11407.23,5320 h60
  text "EXTERNAL" at 13139.46,5320 h60
  text "PER" at 11607.23,5202 h60
  text "IPC-D-275 CLASS 2 LEVEL C" at 11827.23,5202 h60
  text "MIL, HOLES" at 13315.46,5089.71 h60
  text "+/-" at 12923,5089 h60
  text "+/-" at 13777,5089 h60
  text "REGISTRATION TOLERANCES:" at 11407.23,5084 h60
  text "METAL" at 12607,5084 h60
  text "5" at 13183.2,5084 h60
  text "3" at 14016.2,5084 h60
  text "MIL" at 14132.46,5084 h60
  text "MATERIAL:" at 11332.46,4874.54 h60
  text "FR-4 High Tg" at 12318.9,4734.21 h60
  text "FR-408" at 11753.46,4725.64 h60
  text "X" at 12165.46,4725.64 h60
  text "OTHER" at 13241.46,4725.64 h60
  text "62 MIL (1.6mm) +/-10%" at 12073.56,4562.92 h60
  text "THICKNESS:" at 11407.23,4558.64 h60
  text "X" at 11945.4,4558.64 h60
  text "OTHER" at 13358.46,4558.64 h60
  text "TOLERANCE:" at 11407.23,4400.64 h60
  text "X" at 12246.53,4400.64 h60
  text "ANSI IPC-6012 TYPE 3 CLASS 2" at 12433.48,4400.64 h60
  text "OTHER +/-" at 12433.46,4244.64 h60
  text "BOW & TWIST:" at 11407.23,4087.64 h60
  text "X" at 12246.53,4087.64 h60
  text "ANSI IPC-6012 TYPE 3 CLASS 2" at 12433.48,4087.64 h60
  text "OTHER +/-" at 12433.46,3929.13 h60
  text "DRILLING:" at 11332.46,3790.64 h60
  text "REFERENCE:" at 11407.23,3673.64 h60
  text "X" at 12055.46,3673.64 h60
  text "AS SHOWN" at 12242.46,3673.64 h60
  text "X" at 12956.46,3673.64 h60
  text "NC_DRILL FILES" at 13093.46,3673.64 h60
  text "PTH MIN COPPER THICKNESS:" at 11407.23,3515.64 h60
  text "X" at 12757.46,3515.64 h60
  text "1MIL" at 12894.46,3515.64 h60
  text "OTHER" at 13391.46,3515.64 h60
  text "BOARD FINISH:" at 11332.46,3356.64 h60
  text "SILKSCREEN:" at 11487.68,3238.64 h60
  text "X" at 12436.46,3238.64 h60
  text "TOP" at 12562.46,3238.64 h60
  text "X" at 12946.46,3238.64 h60
  text "BOTTOM" at 13073.46,3238.64 h60
  text "SILKSCREEN COLOR:" at 11487.68,3071.64 h60
  text "X" at 12435.42,3071.64 h60
  text "WHITE" at 12562.46,3071.64 h60
  text "OTHER" at 13073.46,3071.64 h60
  text "SOLDER RESIST COLOR:" at 11487.68,2901.64 h60
  text "X" at 12055.42,2742.44 h60
  text "GREEN" at 12182.46,2742.44 h60
  text "BLUE" at 12773.46,2742.44 h60
  text "OTHER" at 13311.46,2742.44 h60
  text "IMMERSION GOLD (ENIG)" at 12393.46,2553.92 h60
  text "ENEPIG" at 13731,2550.64 h60
  text "SURFACE FINISH:" at 11332.46,2549.64 h60
  text "IMM. TIN/SILVER OR EQUIV" at 11662,2392.64 h60
  text "OTHER" at 13093.46,2392.64 h60
  text "X" at 11500,2390 h60
  text "ARRAY/PANEL:" at 11332.46,2213.64 h60
  text "CUT AND TRIM PER MECH LAYER 1" at 12393.46,2209.35 h60
  text "N.C. ROUTE" at 12393.46,2057.64 h60
  text "X" at 13072.46,2057.64 h60
  text "V. SCORE" at 13259.46,2057.64 h60
  text "CERTIFICATION:" at 11332.46,1920.64 h60
  text "MATERIALS AND WORKMANSHIP FOR ALL PCBS" at 12057.46,1920.64 h60
  text "TO MEET OR EXCEED THE REQUIREMENTS OF:" at 12057.46,1822.64 h60
  text "X" at 11683.96,1686.13 h60
  text "ANSI IPC-A-600F CLASS ->" at 11822.96,1686.13 h60
  text "X" at 13462.02,1686.13 h60
  text "2" at 13580.96,1686.14 h60
  text "1" at 13265.96,1684.64 h60
  text "3" at 13934.96,1684.64 h60
  text "X" at 11686.02,1526.64 h60
  text "UL 94V-0" at 11822.96,1526.64 h60
  text "X" at 12498.02,1526.64 h60
  text "RoHS" at 12634.96,1526.64 h60
  text "OTHER" at 13279.36,1526.64 h60
  text "PER ORDER" at 13676.42,1526.64 h60
  text "ADDITIONAL REQUIREMENTS:" at 11332.46,1385.64 h60
  text "MICROSECTION:" at 11407.23,1270.64 h60
  text "YES" at 12312.96,1270.64 h60
  text "REQUIRED" at 13174.46,1114.49 h60
  text "BARE BOARD ELEC. TEST:" at 11407.23,1111.64 h60
  text "NONE" at 12712.96,1111.64 h60
  text "PER ORDER" at 13766.46,1111.64 h60
  text "X" at 12590,1110 h60
  text "MANUFACTURER'S UL:" at 11407.23,954.64 h60
  text "RAIL" at 12572.96,950.35 h60
  text "METAL" at 13064.77,950.35 h60
  text "X" at 13440,950 h60
  text "SILK" at 13576.46,950.35 h60
  text ".Layer_Name" at 577,-858.49 h60
M11 Gerber Information:
  lines w10: -292,-930.17 6308,-930.17 ; -292,-726.83 6310,-726.83 ; -292,-523.5 -292,-1133.5 3713,-1133.5 6310,-1133.5 6310,-523.5 -291.5,-523.5 -291.5,-1133.5 1284,-1133.5 ; 2173,-1133.5 2173,-523.5 ; 3440,-726.83 3440,-523.5 ; 4280,-726.83 4280,-523.5 ; 4902,-1140 4902,-937.17
  text "ALL ARTWORK VIEWED FROM TOP SIDE" at -228.5,-655.67 h60
  text "BOARD #:" at 2248,-655.67 h60
  text ".PRJ_Number" at 2793.5,-655.67 h60
  text "REV:" at 3638,-655.67 h60
  text ".PCB_Rev" at 3929.5,-655.67 h60
  text "SVN REV:" at 4476,-655.67 h60
  text ".VersionControl_RevNumber" at 4982,-655.67 h60
  text "LAYER NAME =" at -228.5,-858.49 h60
  text "TID #:" at 2248,-859 h60
  text ".TID" at 2793.5,-859 h60
  text "PLOT NAME =" at -228.5,-1064.34 h60
  text ".plot_File_Name" at 577,-1064.34 h60
  text "GENERATED    :" at 2250,-1064.34 h60
  text ".Print_Date" at 3119.5,-1064.34 h60
  text ".Print_Time" at 3848.5,-1064.34 h60
  text "TEXAS INSTRUMENTS" at 5113,-1064.34 h60
M12 Stackup:
  drawing of 191 lines, arcs and shapes, not listed
  text "Layer" at 9790.58,7830 h60
  text "Name" at 10200.49,7830 h60
  text "Material" at 11130.23,7830 h60
  text "Thickness" at 11990,7830 h60
  text "Constant" at 12639.84,7830 h60
  text "Board Layer Stack" at 13209.7,7830 h60
  text "1" at 9790.58,7710 h60
  text "Top Overlay" at 10200.49,7710 h60
  text "2" at 9790.58,7590 h60
  text "Top Solder" at 10200.49,7590 h60
  text "Solder Resist" at 11130.23,7590 h60
  text "0.40mil" at 11990,7590 h60
  text "3.5" at 12639.84,7590 h60
  text "3" at 9790.58,7470 h60
  text "Top Layer" at 10200.49,7470 h60
  text "Copper" at 11130.23,7470 h60
  text "1.40mil" at 11990,7470 h60
  text "4" at 9790.58,7350 h60
  text "Dielectric1" at 10200.49,7350 h60
  text "FR-4" at 11130.23,7350 h60
  text "59.20mil" at 11990,7350 h60
  text "4.8" at 12639.84,7350 h60
  text "5" at 9790.58,7230 h60
  text "Bottom Layer" at 10200.49,7230 h60
  text "Copper" at 11130.23,7230 h60
  text "1.40mil" at 11990,7230 h60
  text "6" at 9790.58,7110 h60
  text "Bottom Solder" at 10200.49,7110 h60
  text "Solder Resist" at 11130.23,7110 h60
  text "0.40mil" at 11990,7110 h60
  text "3.5" at 12639.84,7110 h60
  text "7" at 9790.58,6990 h60
  text "Bottom Overlay" at 10200.49,6990 h60
  text ".Layer_Name" at 577,-858.49 h60
M13 Component Bodies Top:
  text ".Layer_Name" at 577,-858.49 h60
M14 Component Bodies Bottom:
  text ".Layer_Name" at 577,-858.49 h60
M15 Courtyards Top:
  text ".Layer_Name" at 577,-858.49 h60
M16 Courtyards Bottom:
  text ".Layer_Name" at 577,-858.49 h60
Drill Drawing:
  circle w1: c5572.8,3071.37 r24.91
  lines w1: 5547.89,2448.63 5547.89,2461.08 5560.35,2473.54 5547.89,2485.99 5547.89,2498.45 5560.35,2498.45 5572.8,2485.99 5585.26,2498.45 5597.71,2498.45 5597.71,2485.99 5585.26,2473.54 5597.71,2461.08 5597.71,2448.63 5585.26,2448.63 5572.8,2461.08 5560.35,2448.63 5547.89,2448.63 ; 5547.89,2598.09 5572.8,2610.54 5597.71,2598.09 5585.26,2623 5597.71,2647.9 5572.8,2635.45 5547.89,2647.9 5560.35,2623 5547.89,2598.09 ; 5547.89,2760 5560.35,2760 5572.8,2747.54 5585.26,2760 5597.71,2760 5585.26,2772.45 5597.71,2784.91 5585.26,2784.91 5572.8,2797.36 5560.35,2784.91 5547.89,2784.91 5560.35,2772.45 5547.89,2760 ; 5547.89,2946.82 5597.71,2946.82 5572.8,2897 5547.89,2946.82 ; 5547.89,3195.92 5597.71,3195.92 5597.71,3245.74 5547.89,3245.74 5547.89,3195.92
  lines w12: 5480,2403.79 7599.4,2403.79 ; 5480,3300.54 7599.4,3300.54 ; 5850.67,2254.33 5850.67,3450 ; 6207.78,2254.33 6207.78,3450 ; 6869.79,2254.33 6869.79,3450 ; 7154.14,2254.33 7154.14,3450 ; 5480,2254.33 7599.4,2254.33 7599.4,3450 5480,3450 5480,2254.33
  text "Symbol" at 5569.68,3345.38 h72
  text "Quantity" at 5895.51,3345.38 h72
  text "Finished Hole Size" at 6252.62,3345.38 h72
  text "Plated" at 6914.62,3345.38 h72
  text "Hole Type" at 7198.98,3345.38 h72
  text "6" at 5895.51,3195.92 h60
  text "10.00mil (0.254mm)" at 6252.62,3195.92 h60
  text "PTH" at 6914.62,3195.92 h60
  text "Round" at 7198.98,3195.92 h60
  text "2" at 5895.51,3046.46 h60
  text "33.00mil (0.838mm)" at 6252.62,3046.46 h60
  text "PTH" at 6914.62,3046.46 h60
  text "Round" at 7198.98,3046.46 h60
  text "2" at 5895.51,2897 h60
  text "37.40mil (0.950mm)" at 6252.62,2897 h60
  text "PTH" at 6914.62,2897 h60
  text "Round" at 7198.98,2897 h60
  text "8" at 5895.51,2747.54 h60
  text "39.37mil (1.000mm)" at 6252.62,2747.54 h60
  text "PTH" at 6914.62,2747.54 h60
  text "Round" at 7198.98,2747.54 h60
  text "6" at 5895.51,2598.09 h60
  text "40.00mil (1.016mm)" at 6252.62,2598.09 h60
  text "PTH" at 6914.62,2598.09 h60
  text "Round" at 7198.98,2598.09 h60
  text "2" at 5895.51,2448.63 h60
  text "62.99mil (1.600mm)" at 6252.62,2448.63 h60
  text "PTH" at 6914.62,2448.63 h60
  text "Round" at 7198.98,2448.63 h60
  text "26 Total" at 5895.51,2299.17 h60
  text ".Layer_Name" at 577,-858.49 h60

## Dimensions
0,0 to 1771.65,0 on M2 Board Dimensions
0,0 to 0,1496.06 on M2 Board Dimensions
0,-400 to 1000,-400 on M2 Board Dimensions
